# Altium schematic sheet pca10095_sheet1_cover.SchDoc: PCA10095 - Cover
size A3; Organization: Nordic Semiconductor; DocumentNumber: 1; SheetNumber: 1; SheetTotal: 6; CompanyName: Nordic Semiconductor
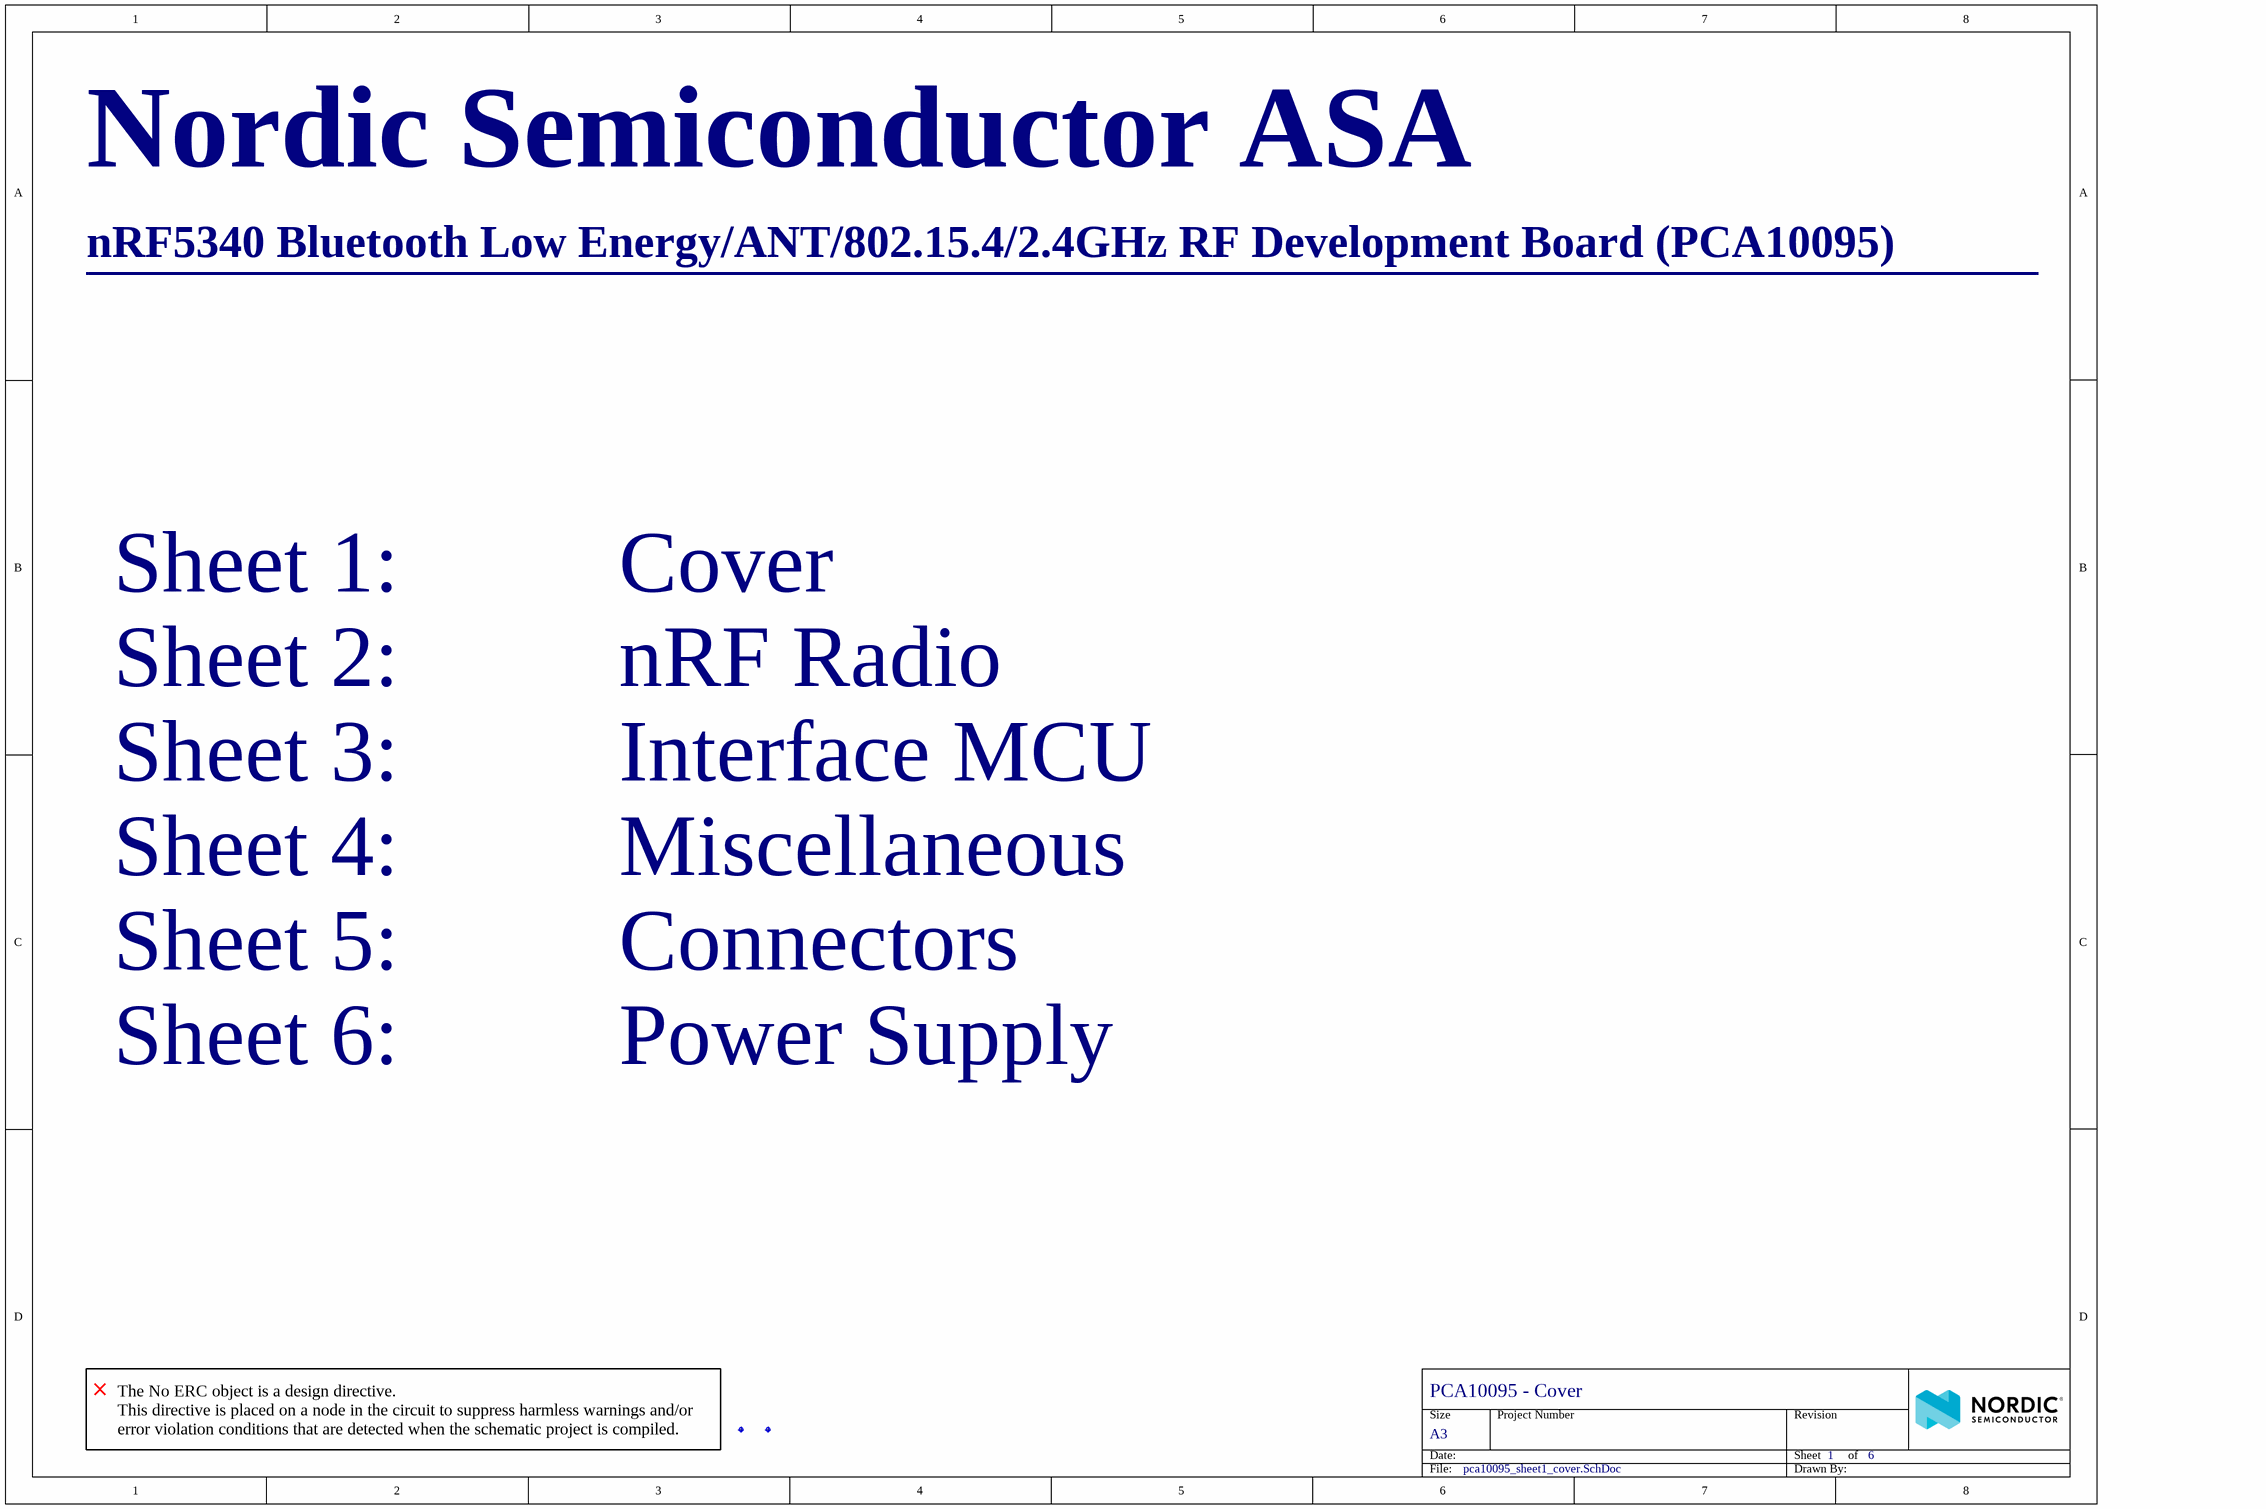
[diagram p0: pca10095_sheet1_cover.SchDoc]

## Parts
Fid1  Fiducial mark  [Fiducial]  (value not drawn)
Fid2  Fiducial mark  [Fiducial]  (value not drawn)

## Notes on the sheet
- Nordic Semiconductor ASA
- nRF5340 Bluetooth Low Energy/ANT/802.15.4/2.4GHz RF Development Board (PCA10095)
- ________________________________________________________________
- Sheet 1:          Cover
- Sheet 2:          nRF Radio
- Sheet 3:          Interface MCU
- Sheet 4:          Miscellaneous
- Sheet 5:          Connectors
- Sheet 6:          Power Supply
- (near Fid1) The No ERC object is a design directive.
  This directive is placed on a node in the circuit to suppress harmless warnings and/or error violation conditions that are detected when the schematic project is compiled.

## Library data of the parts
Fid1 Fid2 = Fid-Mark: Artikkelnr Noca: N.A.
